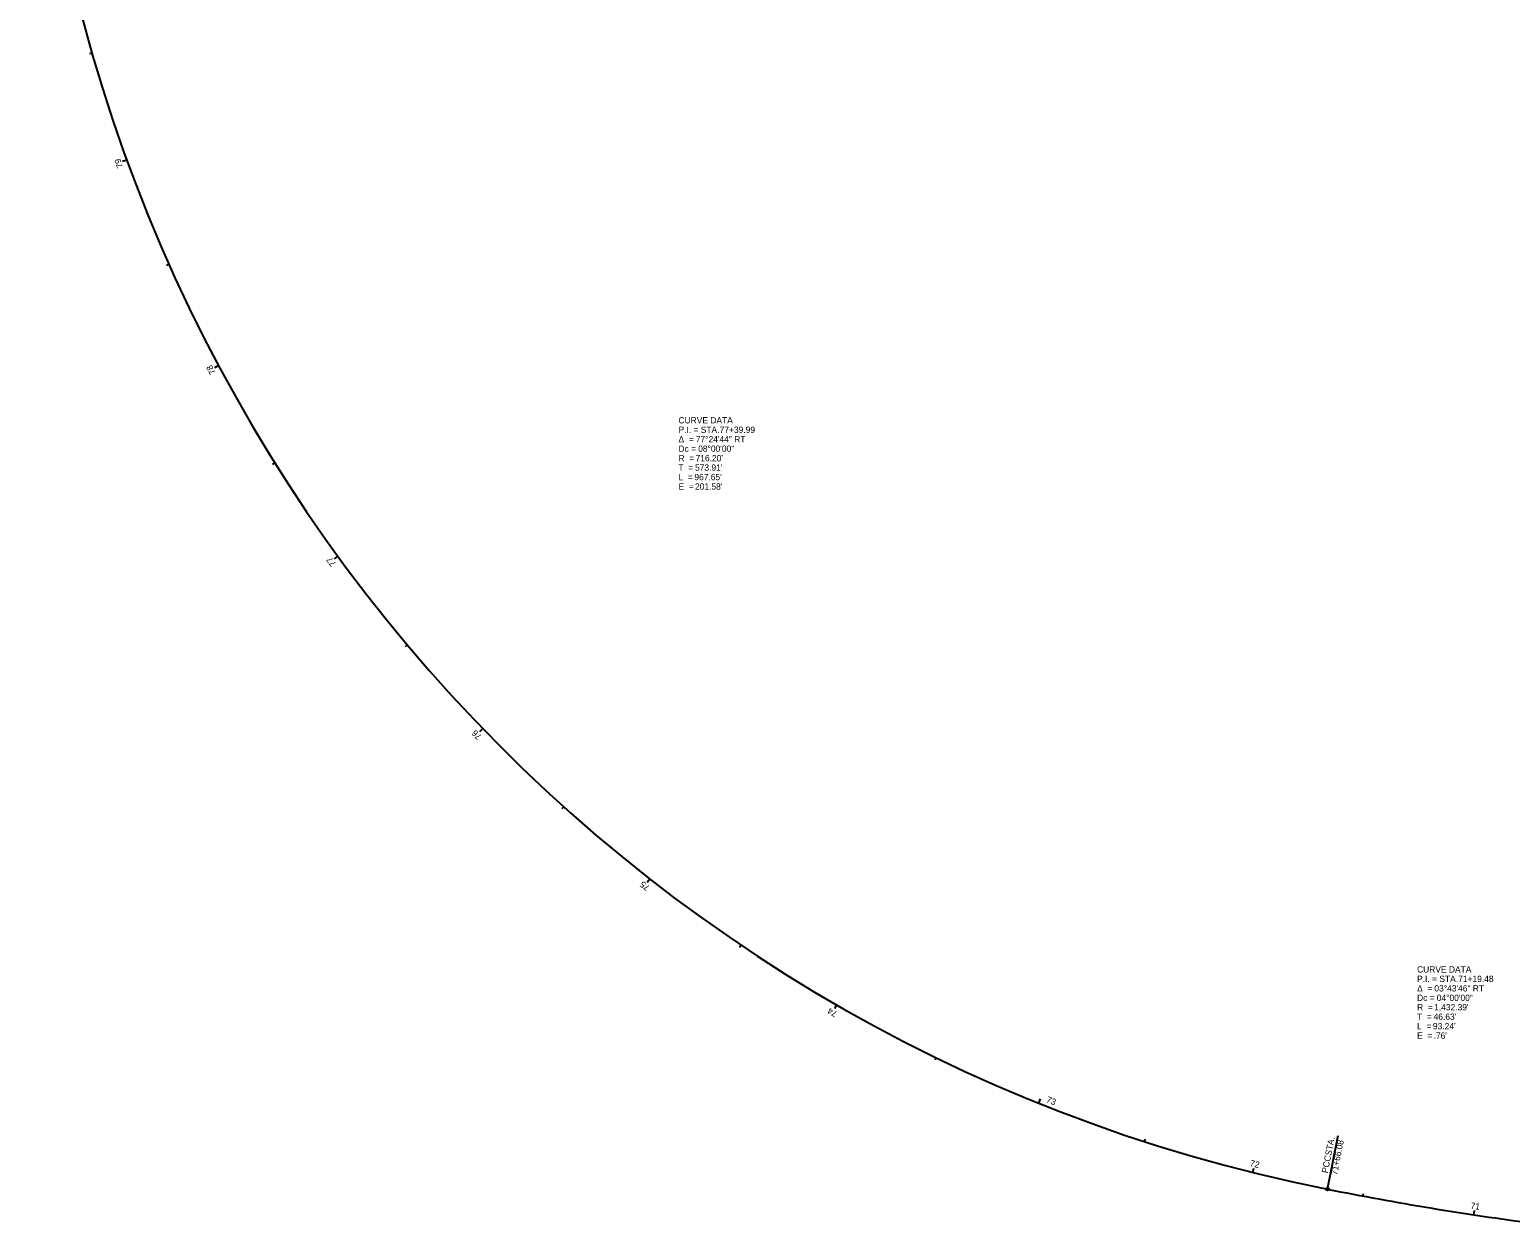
# Model space of a CAD drawing. Extents: x 2203357 to 2204663, y 635542 to 636605.
# Drawn here: x 2203362 to 2204020, y 635566 to 636096 of the extents above; entities that cross this region are included whole.
import ezdxf

# ---------------------------------------------------------------- set-up
doc = ezdxf.new("R2010")
doc.units = 0
for name, color, linetype in [('RW_X_CL', 7, 'Continuous'), ('SH_Border', 7, 'Continuous'), ('SH_Cut_Line', 7, 'Continuous'), ('SH_Data', 7, 'Continuous')]:
    doc.layers.add(name, color=color, linetype=linetype)

msp = doc.modelspace()

# ---------------------------------------------------------------- linework, layer by layer
at = {"layer": 'RW_X_CL'}
for p, q in [((2203389.78, 636085.56), (2203388.63, 636085.23)), ((2203405.27, 636038.03), (2203403.39, 636037.34)), ((2203424.04, 635991.7), (2203422.94, 635991.21)), ((2203445.99, 635946.78), (2203444.23, 635945.84)), ((2203471.02, 635903.51), (2203470.01, 635902.88)), ((2203499.01, 635862.09), (2203497.4, 635860.92)), ((2203529.82, 635822.73), (2203528.91, 635821.96)), ((2203563.31, 635785.61), (2203561.87, 635784.22)), ((2203599.3, 635750.91), (2203598.49, 635750.02)), ((2203637.62, 635718.81), (2203636.39, 635717.24)), ((2203678.09, 635689.46), (2203677.42, 635688.47)), ((2203720.5, 635663.01), (2203719.5, 635661.28)), ((2203764.66, 635639.58), (2203764.14, 635638.5)), ((2203810.35, 635619.29), (2203811.09, 635621.14)), ((2203857.34, 635602.23), (2203857.71, 635603.37)), ((2203905.4, 635588.49), (2203905.88, 635590.43)), ((2203954.29, 635578.05), (2203954.51, 635579.23)), ((2204003.59, 635569.72), (2204003.89, 635571.7))]:
    msp.add_line(p, q, dxfattribs=at)
at = {"layer": 'SH_Cut_Line'}
for centre, radius, start, end in [((2204078.07, 636283.56), 716.2, 181.35056, 258.76282), ((2204078.07, 636283.56), 716.2, 181.35056, 258.76282), ((2204078.07, 636283.56), 716.2, 181.35056, 258.76282), ((2204217.63, 636986.03), 1432.39, 258.76282, 262.4923), ((2204217.63, 636986.03), 1432.39, 258.76282, 262.4923), ((2204217.63, 636986.03), 1432.39, 258.76282, 262.4923)]:
    msp.add_arc(centre, radius, start, end, dxfattribs=at)
at = {"layer": 'SH_Data'}
msp.add_line((2203938.5, 635581.1), (2203943.25, 635604.98), dxfattribs=at)
msp.add_circle((2203938.5, 635581.1), 0.6, dxfattribs=at)

# ---------------------------------------------------------------- texts
at = {"layer": 'RW_X_CL'}
for s, rotation, p in [('79', 110.04942, (2203403.68, 636035.1)), ('78', 118.04942, (2203444.83, 635943.65)), ('77', 126.04942, (2203498.35, 635858.76)), ('76', 134.04942, (2203563.07, 635782.26)), ('75', 142.04942, (2203637.81, 635715.5)), ('74', 150.04942, (2203721.12, 635659.77)), ('73', 338.04942, (2203813.4, 635619.82)), ('72', 346.04942, (2203903.91, 635591.44)), ('71', 351.40612, (2204001.95, 635572.49))]:
    msp.add_text(s, height=2.8, rotation=rotation, dxfattribs=at).set_placement(p)
at = {"layer": 'SH_Border'}
for s, p in [('CURVE DATA', (2203650.28, 635921.09)), ('P.I. = STA. ', (2203650.28, 635916.89)), ('77+39.99', (2203668.55, 635916.89)), ('Δ  = ', (2203650.28, 635912.69)), ('Dc = ', (2203650.28, 635908.49)), ('77°24\'44" RT', (2203657.96, 635912.69)), ('08°00\'00"', (2203659.02, 635908.49)), ('R  = ', (2203650.28, 635904.29)), ("716.20'", (2203657.87, 635904.29)), ('T  = ', (2203650.28, 635900.09)), ('L  = ', (2203650.28, 635895.89)), ("967.65'", (2203657.33, 635895.89)), ("573.91'", (2203657.62, 635900.09)), ('E  = ', (2203650.28, 635891.69)), ("201.58'", (2203657.62, 635891.69)), ('CURVE DATA', (2203978.34, 635677.28)), ('P.I. = STA. ', (2203978.34, 635673.08)), ('71+19.48', (2203996.6, 635673.08)), ('Δ  = ', (2203978.34, 635668.88)), ('Dc = ', (2203978.34, 635664.68)), ('03°43\'46" RT', (2203986.01, 635668.88)), ('04°00\'00"', (2203987.07, 635664.68)), ('R  = ', (2203978.34, 635660.48)), ("1,432.39'", (2203985.92, 635660.48)), ('T  = ', (2203978.34, 635656.28)), ('L  = ', (2203978.34, 635652.08)), ("93.24'", (2203985.38, 635652.08)), ("46.63'", (2203985.67, 635656.28)), ('E  = ', (2203978.34, 635647.88)), (".76'", (2203985.68, 635647.88))]:
    msp.add_text(s, height=2.8, dxfattribs=at).set_placement(p)
at = {"layer": 'SH_Data'}
for s, p in [(' STA. ', (2203939.99, 635594.8)), ('71+66.08', (2203942.77, 635587.23)), ('PCC', (2203938.65, 635588.05))]:
    msp.add_text(s, height=2.8, rotation=78.76282, dxfattribs=at).set_placement(p)

doc.saveas('drawing.dxf')
